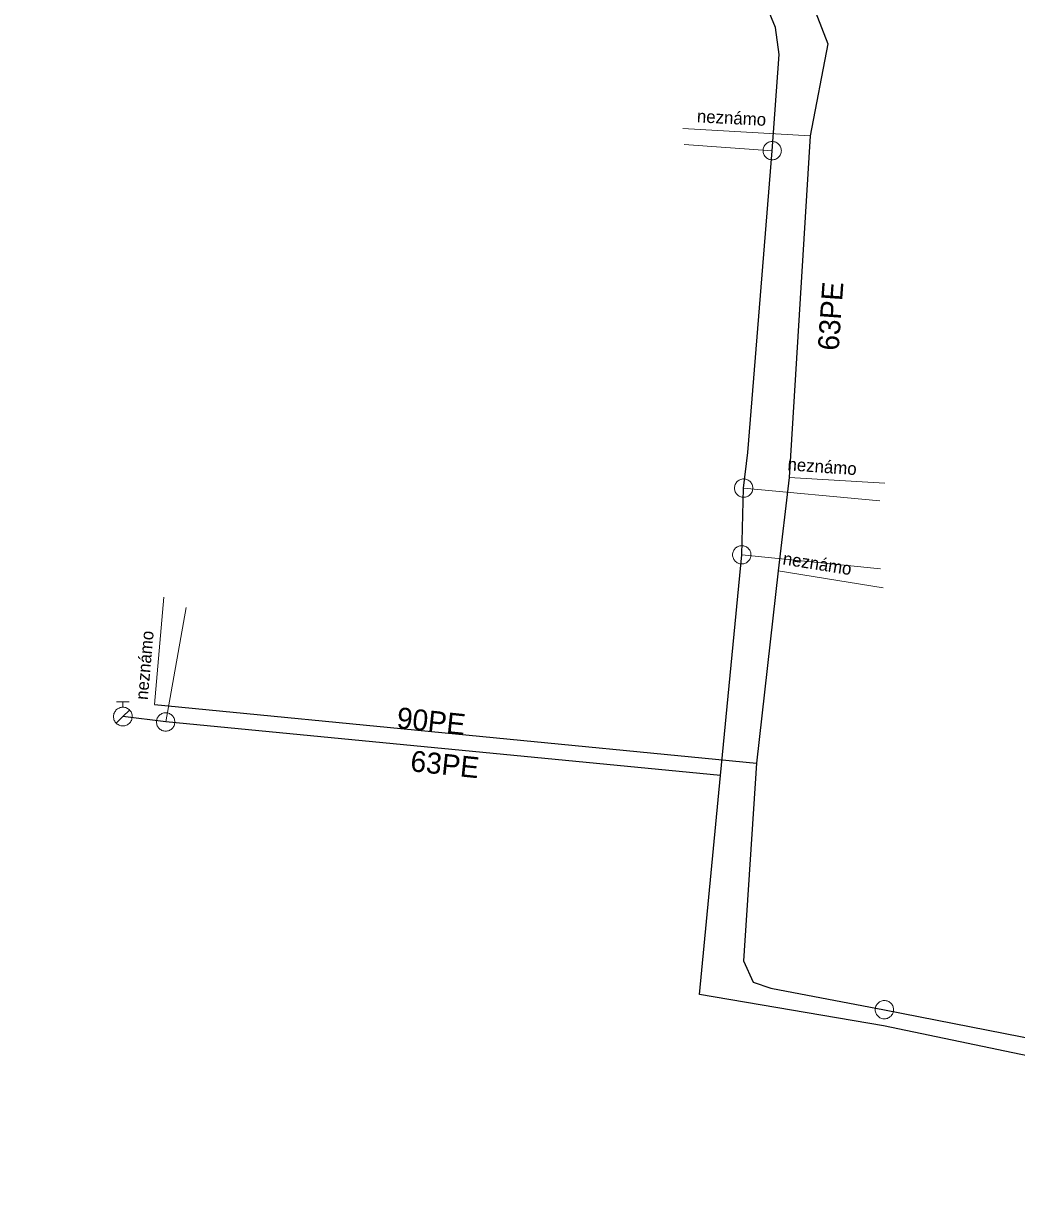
# Model space of a CAD drawing. Extents: x -741806 to -738704, y -1059275 to -1055387.
# Drawn here: x -740703.1 to -740655.8, y -1057566.4 to -1057510.5 of the extents above; entities that cross this region are included whole.
import ezdxf

# ---------------------------------------------------------------- set-up
doc = ezdxf.new("R2010")
doc.units = 0
doc.header["$LTSCALE"] = 0.4
for name, color, linetype, lineweight in [('2', 7, 'Continuous', 25), ('21', 7, 'Continuous', 13), ('3', 7, 'Continuous', 13), ('50', 7, 'Continuous', 13), ('51', 7, 'Continuous', 13), ('52', 7, 'Continuous', 25), ('56', 7, 'Continuous', 13)]:
    doc.layers.add(name, color=color, linetype=linetype, lineweight=lineweight)
for name, color, linetype in [('5', 7, 'Continuous'), ('53', 7, 'Continuous'), ('55', 7, 'Continuous')]:
    doc.layers.add(name, color=color, linetype=linetype)

msp = doc.modelspace()

# ---------------------------------------------------------------- linework, layer by layer
at = {"layer": '2'}
msp.add_line((-740696.899, -1057542.97), (-740668.18, -1057545.78), dxfattribs=at)
msp.add_lwpolyline([(-740701.18, -1057473.159), (-740698.129, -1057473.58), (-740689.684, -1057473.824), (-740686.82, -1057473.879), (-740685.879, -1057474.169), (-740685.34, -1057475.12), (-740682.62, -1057479.69), (-740667.039, -1057506.61), (-740665.579, -1057509.429), (-740664.78, -1057511.48), (-740665.629, -1057515.87), (-740666.629, -1057532.149), (-740667.16, -1057536.6), (-740668.18, -1057545.78), (-740668.8, -1057555.2), (-740668.35, -1057556.21), (-740667.51, -1057556.51), (-740662.09, -1057557.53), (-740650.66, -1057559.78), (-740647.78, -1057560.7), (-740633.18, -1057564.139), (-740633.142, -1057565.869)], dxfattribs=at)
at = {"layer": '21'}
for p, q in [((-740667.44, -1057516.57), (-740671.64, -1057516.27)), ((-740668.8, -1057532.659), (-740662.309, -1057533.27)), ((-740668.89, -1057535.84), (-740662.27, -1057536.51)), ((-740696.359, -1057543.81), (-740695.379, -1057538.35))]:
    msp.add_line(p, q, dxfattribs=at)
at = {"layer": '3'}
msp.add_lwpolyline([(-740661.659, -1057557.611), (-740661.654, -1057557.566), (-740661.652, -1057557.521), (-740661.656, -1057557.474), (-740661.664, -1057557.43), (-740661.677, -1057557.386), (-740661.694, -1057557.343), (-740661.716, -1057557.303), (-740661.742, -1057557.265), (-740661.772, -1057557.231), (-740661.804, -1057557.199), (-740661.841, -1057557.171), (-740661.88, -1057557.146), (-740661.921, -1057557.127), (-740661.964, -1057557.111), (-740662.009, -1057557.101), (-740662.054, -1057557.094), (-740662.1, -1057557.094), (-740662.145, -1057557.096), (-740662.191, -1057557.105), (-740662.235, -1057557.118), (-740662.277, -1057557.136), (-740662.316, -1057557.157), (-740662.355, -1057557.183), (-740662.39, -1057557.212), (-740662.422, -1057557.246), (-740662.449, -1057557.282), (-740662.473, -1057557.32), (-740662.494, -1057557.362), (-740662.509, -1057557.405), (-740662.519, -1057557.45), (-740662.526, -1057557.495), (-740662.527, -1057557.54), (-740662.524, -1057557.587), (-740662.515, -1057557.632), (-740662.503, -1057557.675), (-740662.485, -1057557.718), (-740662.463, -1057557.758), (-740662.437, -1057557.796), (-740662.408, -1057557.83), (-740662.375, -1057557.862), (-740662.338, -1057557.89), (-740662.299, -1057557.915), (-740662.258, -1057557.935), (-740662.215, -1057557.95), (-740662.171, -1057557.96), (-740662.125, -1057557.967), (-740662.08, -1057557.968), (-740662.034, -1057557.965), (-740661.989, -1057557.956), (-740661.944, -1057557.943), (-740661.902, -1057557.925), (-740661.862, -1057557.905), (-740661.824, -1057557.878), (-740661.789, -1057557.849), (-740661.758, -1057557.815), (-740661.729, -1057557.779), (-740661.706, -1057557.741), (-740661.686, -1057557.699), (-740661.671, -1057557.656), (-740661.659, -1057557.612)], dxfattribs=at)
at = {"layer": '50'}
for p, q in [((-740698.707, -1057542.856), (-740698.399, -1057542.856)), ((-740698.399, -1057543.107), (-740698.399, -1057542.856)), ((-740698.092, -1057542.856), (-740698.399, -1057542.856)), ((-740698.399, -1057543.554), (-740698.083, -1057543.242)), ((-740698.399, -1057543.554), (-740698.716, -1057543.871))]:
    msp.add_line(p, q, dxfattribs=at)
msp.add_lwpolyline([(-740697.955, -1057543.558), (-740697.957, -1057543.509), (-740697.962, -1057543.463), (-740697.975, -1057543.417), (-740697.992, -1057543.374), (-740698.011, -1057543.334), (-740698.038, -1057543.293), (-740698.067, -1057543.258), (-740698.1, -1057543.223), (-740698.135, -1057543.193), (-740698.175, -1057543.169), (-740698.216, -1057543.147), (-740698.259, -1057543.128), (-740698.305, -1057543.118), (-740698.351, -1057543.11), (-740698.397, -1057543.107), (-740698.443, -1057543.11), (-740698.488, -1057543.115), (-740698.534, -1057543.128), (-740698.578, -1057543.145), (-740698.621, -1057543.166), (-740698.659, -1057543.191), (-740698.696, -1057543.22), (-740698.729, -1057543.253), (-740698.758, -1057543.288), (-740698.785, -1057543.328), (-740698.807, -1057543.369), (-740698.823, -1057543.412), (-740698.837, -1057543.458), (-740698.842, -1057543.504), (-740698.848, -1057543.55), (-740698.846, -1057543.598), (-740698.838, -1057543.644), (-740698.827, -1057543.687), (-740698.811, -1057543.733), (-740698.789, -1057543.774), (-740698.765, -1057543.814), (-740698.735, -1057543.849), (-740698.703, -1057543.884), (-740698.665, -1057543.914), (-740698.627, -1057543.938), (-740698.584, -1057543.96), (-740698.541, -1057543.976), (-740698.498, -1057543.99), (-740698.449, -1057543.998), (-740698.403, -1057544.001), (-740698.357, -1057543.998), (-740698.311, -1057543.99), (-740698.265, -1057543.979), (-740698.222, -1057543.963), (-740698.179, -1057543.941), (-740698.141, -1057543.917), (-740698.103, -1057543.887), (-740698.071, -1057543.855), (-740698.041, -1057543.82), (-740698.017, -1057543.779), (-740697.993, -1057543.739), (-740697.976, -1057543.695), (-740697.966, -1057543.65), (-740697.958, -1057543.604)], close=True, dxfattribs=at)
at = {"layer": '51'}
for points in [[(-740667.002, -1057516.57), (-740667.004, -1057516.525), (-740667.012, -1057516.48), (-740667.024, -1057516.435), (-740667.039, -1057516.393), (-740667.061, -1057516.352), (-740667.085, -1057516.313), (-740667.115, -1057516.278), (-740667.147, -1057516.245), (-740667.183, -1057516.217), (-740667.22, -1057516.192), (-740667.262, -1057516.171), (-740667.304, -1057516.154), (-740667.348, -1057516.142), (-740667.394, -1057516.135), (-740667.44, -1057516.133), (-740667.485, -1057516.135), (-740667.531, -1057516.142), (-740667.575, -1057516.154), (-740667.617, -1057516.171), (-740667.659, -1057516.192), (-740667.696, -1057516.217), (-740667.732, -1057516.245), (-740667.764, -1057516.278), (-740667.794, -1057516.313), (-740667.818, -1057516.352), (-740667.84, -1057516.393), (-740667.855, -1057516.435), (-740667.867, -1057516.48), (-740667.875, -1057516.525), (-740667.877, -1057516.571), (-740667.875, -1057516.616), (-740667.867, -1057516.661), (-740667.855, -1057516.706), (-740667.84, -1057516.748), (-740667.818, -1057516.789), (-740667.794, -1057516.828), (-740667.764, -1057516.863), (-740667.732, -1057516.896), (-740667.696, -1057516.924), (-740667.659, -1057516.949), (-740667.617, -1057516.97), (-740667.575, -1057516.987), (-740667.531, -1057516.998), (-740667.485, -1057517.006), (-740667.44, -1057517.008), (-740667.394, -1057517.006), (-740667.348, -1057516.998), (-740667.304, -1057516.987), (-740667.262, -1057516.97), (-740667.22, -1057516.949), (-740667.183, -1057516.924), (-740667.147, -1057516.896), (-740667.115, -1057516.863), (-740667.085, -1057516.828), (-740667.061, -1057516.789), (-740667.039, -1057516.748), (-740667.024, -1057516.706), (-740667.012, -1057516.661), (-740667.004, -1057516.616), (-740667.002, -1057516.571)], [(-740668.363, -1057532.659), (-740668.365, -1057532.614), (-740668.372, -1057532.569), (-740668.384, -1057532.524), (-740668.4, -1057532.482), (-740668.421, -1057532.441), (-740668.446, -1057532.402), (-740668.475, -1057532.367), (-740668.507, -1057532.334), (-740668.543, -1057532.306), (-740668.581, -1057532.281), (-740668.622, -1057532.26), (-740668.665, -1057532.243), (-740668.709, -1057532.231), (-740668.754, -1057532.224), (-740668.8, -1057532.222), (-740668.846, -1057532.224), (-740668.891, -1057532.231), (-740668.935, -1057532.243), (-740668.978, -1057532.26), (-740669.019, -1057532.281), (-740669.057, -1057532.306), (-740669.093, -1057532.334), (-740669.125, -1057532.367), (-740669.154, -1057532.402), (-740669.179, -1057532.441), (-740669.2, -1057532.482), (-740669.216, -1057532.524), (-740669.228, -1057532.569), (-740669.235, -1057532.614), (-740669.238, -1057532.66), (-740669.235, -1057532.705), (-740669.228, -1057532.75), (-740669.216, -1057532.795), (-740669.2, -1057532.837), (-740669.179, -1057532.878), (-740669.154, -1057532.917), (-740669.125, -1057532.952), (-740669.093, -1057532.985), (-740669.057, -1057533.013), (-740669.019, -1057533.038), (-740668.978, -1057533.059), (-740668.935, -1057533.076), (-740668.891, -1057533.087), (-740668.846, -1057533.095), (-740668.8, -1057533.097), (-740668.754, -1057533.095), (-740668.709, -1057533.087), (-740668.665, -1057533.076), (-740668.622, -1057533.059), (-740668.581, -1057533.038), (-740668.543, -1057533.013), (-740668.507, -1057532.985), (-740668.475, -1057532.952), (-740668.446, -1057532.917), (-740668.421, -1057532.878), (-740668.4, -1057532.837), (-740668.384, -1057532.795), (-740668.372, -1057532.75), (-740668.365, -1057532.705), (-740668.363, -1057532.66)], [(-740668.453, -1057535.84), (-740668.455, -1057535.795), (-740668.462, -1057535.75), (-740668.474, -1057535.705), (-740668.49, -1057535.663), (-740668.511, -1057535.622), (-740668.536, -1057535.583), (-740668.565, -1057535.548), (-740668.597, -1057535.515), (-740668.633, -1057535.487), (-740668.671, -1057535.462), (-740668.712, -1057535.441), (-740668.755, -1057535.424), (-740668.799, -1057535.412), (-740668.844, -1057535.405), (-740668.89, -1057535.403), (-740668.936, -1057535.405), (-740668.981, -1057535.412), (-740669.025, -1057535.424), (-740669.068, -1057535.441), (-740669.109, -1057535.462), (-740669.147, -1057535.487), (-740669.183, -1057535.515), (-740669.215, -1057535.548), (-740669.244, -1057535.583), (-740669.269, -1057535.622), (-740669.29, -1057535.663), (-740669.306, -1057535.705), (-740669.318, -1057535.75), (-740669.325, -1057535.795), (-740669.328, -1057535.841), (-740669.325, -1057535.886), (-740669.318, -1057535.931), (-740669.306, -1057535.976), (-740669.29, -1057536.018), (-740669.269, -1057536.059), (-740669.244, -1057536.098), (-740669.215, -1057536.133), (-740669.183, -1057536.166), (-740669.147, -1057536.194), (-740669.109, -1057536.219), (-740669.068, -1057536.24), (-740669.025, -1057536.257), (-740668.981, -1057536.268), (-740668.936, -1057536.276), (-740668.89, -1057536.278), (-740668.844, -1057536.276), (-740668.799, -1057536.268), (-740668.755, -1057536.257), (-740668.712, -1057536.24), (-740668.671, -1057536.219), (-740668.633, -1057536.194), (-740668.597, -1057536.166), (-740668.565, -1057536.133), (-740668.536, -1057536.098), (-740668.511, -1057536.059), (-740668.49, -1057536.018), (-740668.474, -1057535.976), (-740668.462, -1057535.931), (-740668.455, -1057535.886), (-740668.453, -1057535.841)], [(-740695.922, -1057543.81), (-740695.924, -1057543.765), (-740695.931, -1057543.72), (-740695.943, -1057543.675), (-740695.959, -1057543.633), (-740695.98, -1057543.592), (-740696.005, -1057543.553), (-740696.034, -1057543.518), (-740696.066, -1057543.485), (-740696.102, -1057543.457), (-740696.14, -1057543.432), (-740696.181, -1057543.411), (-740696.224, -1057543.394), (-740696.268, -1057543.382), (-740696.313, -1057543.375), (-740696.359, -1057543.373), (-740696.405, -1057543.375), (-740696.45, -1057543.382), (-740696.494, -1057543.394), (-740696.537, -1057543.411), (-740696.578, -1057543.432), (-740696.616, -1057543.457), (-740696.652, -1057543.485), (-740696.684, -1057543.518), (-740696.713, -1057543.553), (-740696.738, -1057543.592), (-740696.759, -1057543.633), (-740696.775, -1057543.675), (-740696.787, -1057543.72), (-740696.794, -1057543.765), (-740696.797, -1057543.811), (-740696.794, -1057543.856), (-740696.787, -1057543.901), (-740696.775, -1057543.946), (-740696.759, -1057543.988), (-740696.738, -1057544.029), (-740696.713, -1057544.068), (-740696.684, -1057544.103), (-740696.652, -1057544.136), (-740696.616, -1057544.164), (-740696.578, -1057544.189), (-740696.537, -1057544.21), (-740696.494, -1057544.227), (-740696.45, -1057544.238), (-740696.405, -1057544.246), (-740696.359, -1057544.248), (-740696.313, -1057544.246), (-740696.268, -1057544.238), (-740696.224, -1057544.227), (-740696.181, -1057544.21), (-740696.14, -1057544.189), (-740696.102, -1057544.164), (-740696.066, -1057544.136), (-740696.034, -1057544.103), (-740696.005, -1057544.068), (-740695.98, -1057544.029), (-740695.959, -1057543.988), (-740695.943, -1057543.946), (-740695.931, -1057543.901), (-740695.924, -1057543.856), (-740695.922, -1057543.811)]]:
    msp.add_lwpolyline(points, dxfattribs=at)
at = {"layer": '52'}
for points in [[(-740669.903, -1057546.362), (-740668.89, -1057535.84), (-740668.8, -1057532.659), (-740668.6, -1057530.96), (-740667.44, -1057516.57), (-740667.109, -1057511.99), (-740667.289, -1057510.7), (-740668.399, -1057507.99), (-740683.739, -1057481.02), (-740686.96, -1057476.45), (-740689.02, -1057475.889), (-740697.39, -1057475.629), (-740700.809, -1057475.34), (-740703.14, -1057474.73)], [(-740669.903, -1057546.362), (-740696.359, -1057543.81), (-740698.399, -1057543.55)], [(-740622.261, -1057566.439), (-740622.739, -1057566.399), (-740633.96, -1057565.02), (-740651.25, -1057560.57), (-740662.129, -1057558.3), (-740670.91, -1057556.8), (-740669.903, -1057546.362)]]:
    msp.add_lwpolyline(points, dxfattribs=at)
at = {"layer": '56'}
for p, q in [((-740671.699, -1057515.51), (-740665.629, -1057515.87)), ((-740662.07, -1057532.429), (-740666.629, -1057532.149)), ((-740662.14, -1057537.419), (-740667.16, -1057536.6)), ((-740696.44, -1057537.86), (-740696.899, -1057542.97))]:
    msp.add_line(p, q, dxfattribs=at)

# ---------------------------------------------------------------- texts
at = {"layer": '5'}
for rotation, p in [(86, (-740664.27, -1057526.127)), (354, (-740684.723, -1057546.155))]:
    msp.add_text('63PE', height=1, rotation=rotation, dxfattribs=at).set_placement(p)
at = {"layer": '53'}
msp.add_text('90PE', height=1, rotation=354, dxfattribs=at).set_placement((-740685.375, -1057544.096))
at = {"layer": '55'}
for rotation, p in [(357, (-740671.04, -1057515.217)), (356, (-740666.724, -1057531.812)), (351, (-740666.964, -1057536.296)), (85, (-740697.214, -1057542.775))]:
    msp.add_text('neznámo ', height=0.6, rotation=rotation, dxfattribs=at).set_placement(p)

doc.saveas('drawing.dxf')
